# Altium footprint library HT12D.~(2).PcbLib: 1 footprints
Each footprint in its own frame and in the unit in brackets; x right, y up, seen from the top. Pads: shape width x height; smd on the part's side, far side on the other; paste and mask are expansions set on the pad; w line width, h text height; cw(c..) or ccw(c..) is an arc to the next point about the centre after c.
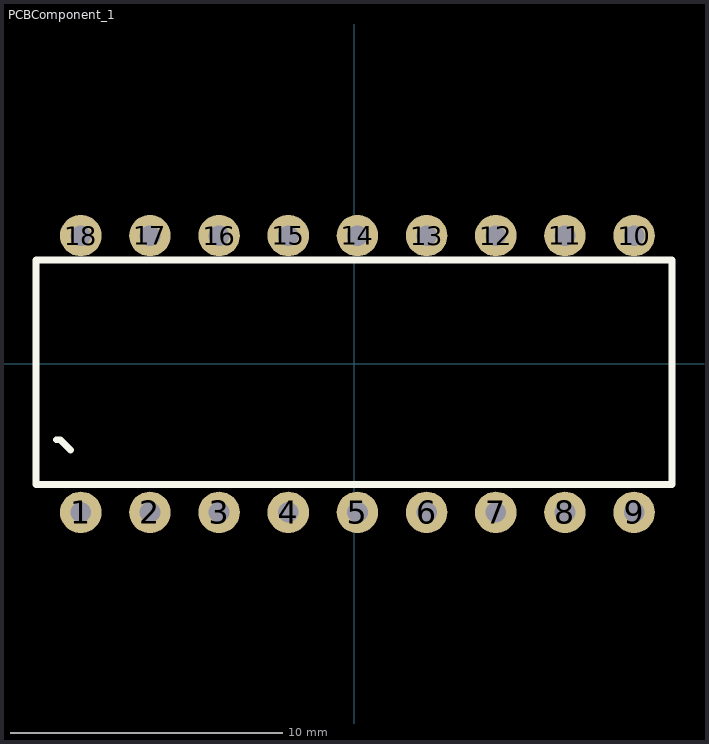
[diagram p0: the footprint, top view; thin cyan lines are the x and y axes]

## PCBComponent_1 [mil]
pads (18):
  round 60 hole 30: 1(-395,-215) 2(-295,-215) 3(-195,-215) 4(-95,-215) 5(5,-215) 6(105,-215) 7(205,-215) 8(305,-215) 9(405,-215) 10(405,185) 11(305,185) 12(205,185) 13(105,185) 14(5,185) 15(-95,185) 16(-195,185) 17(-295,185) 18(-395,185)
Top Overlay:
  lines w10: -430,-110 -425,-110 -410,-125 ; -460,-175 -460,150 460,150 460,-175 -460,-175
3D body: height 325, standoff 0, extent -460,-175 455,150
